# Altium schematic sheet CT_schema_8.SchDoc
size 385 x 278 mm
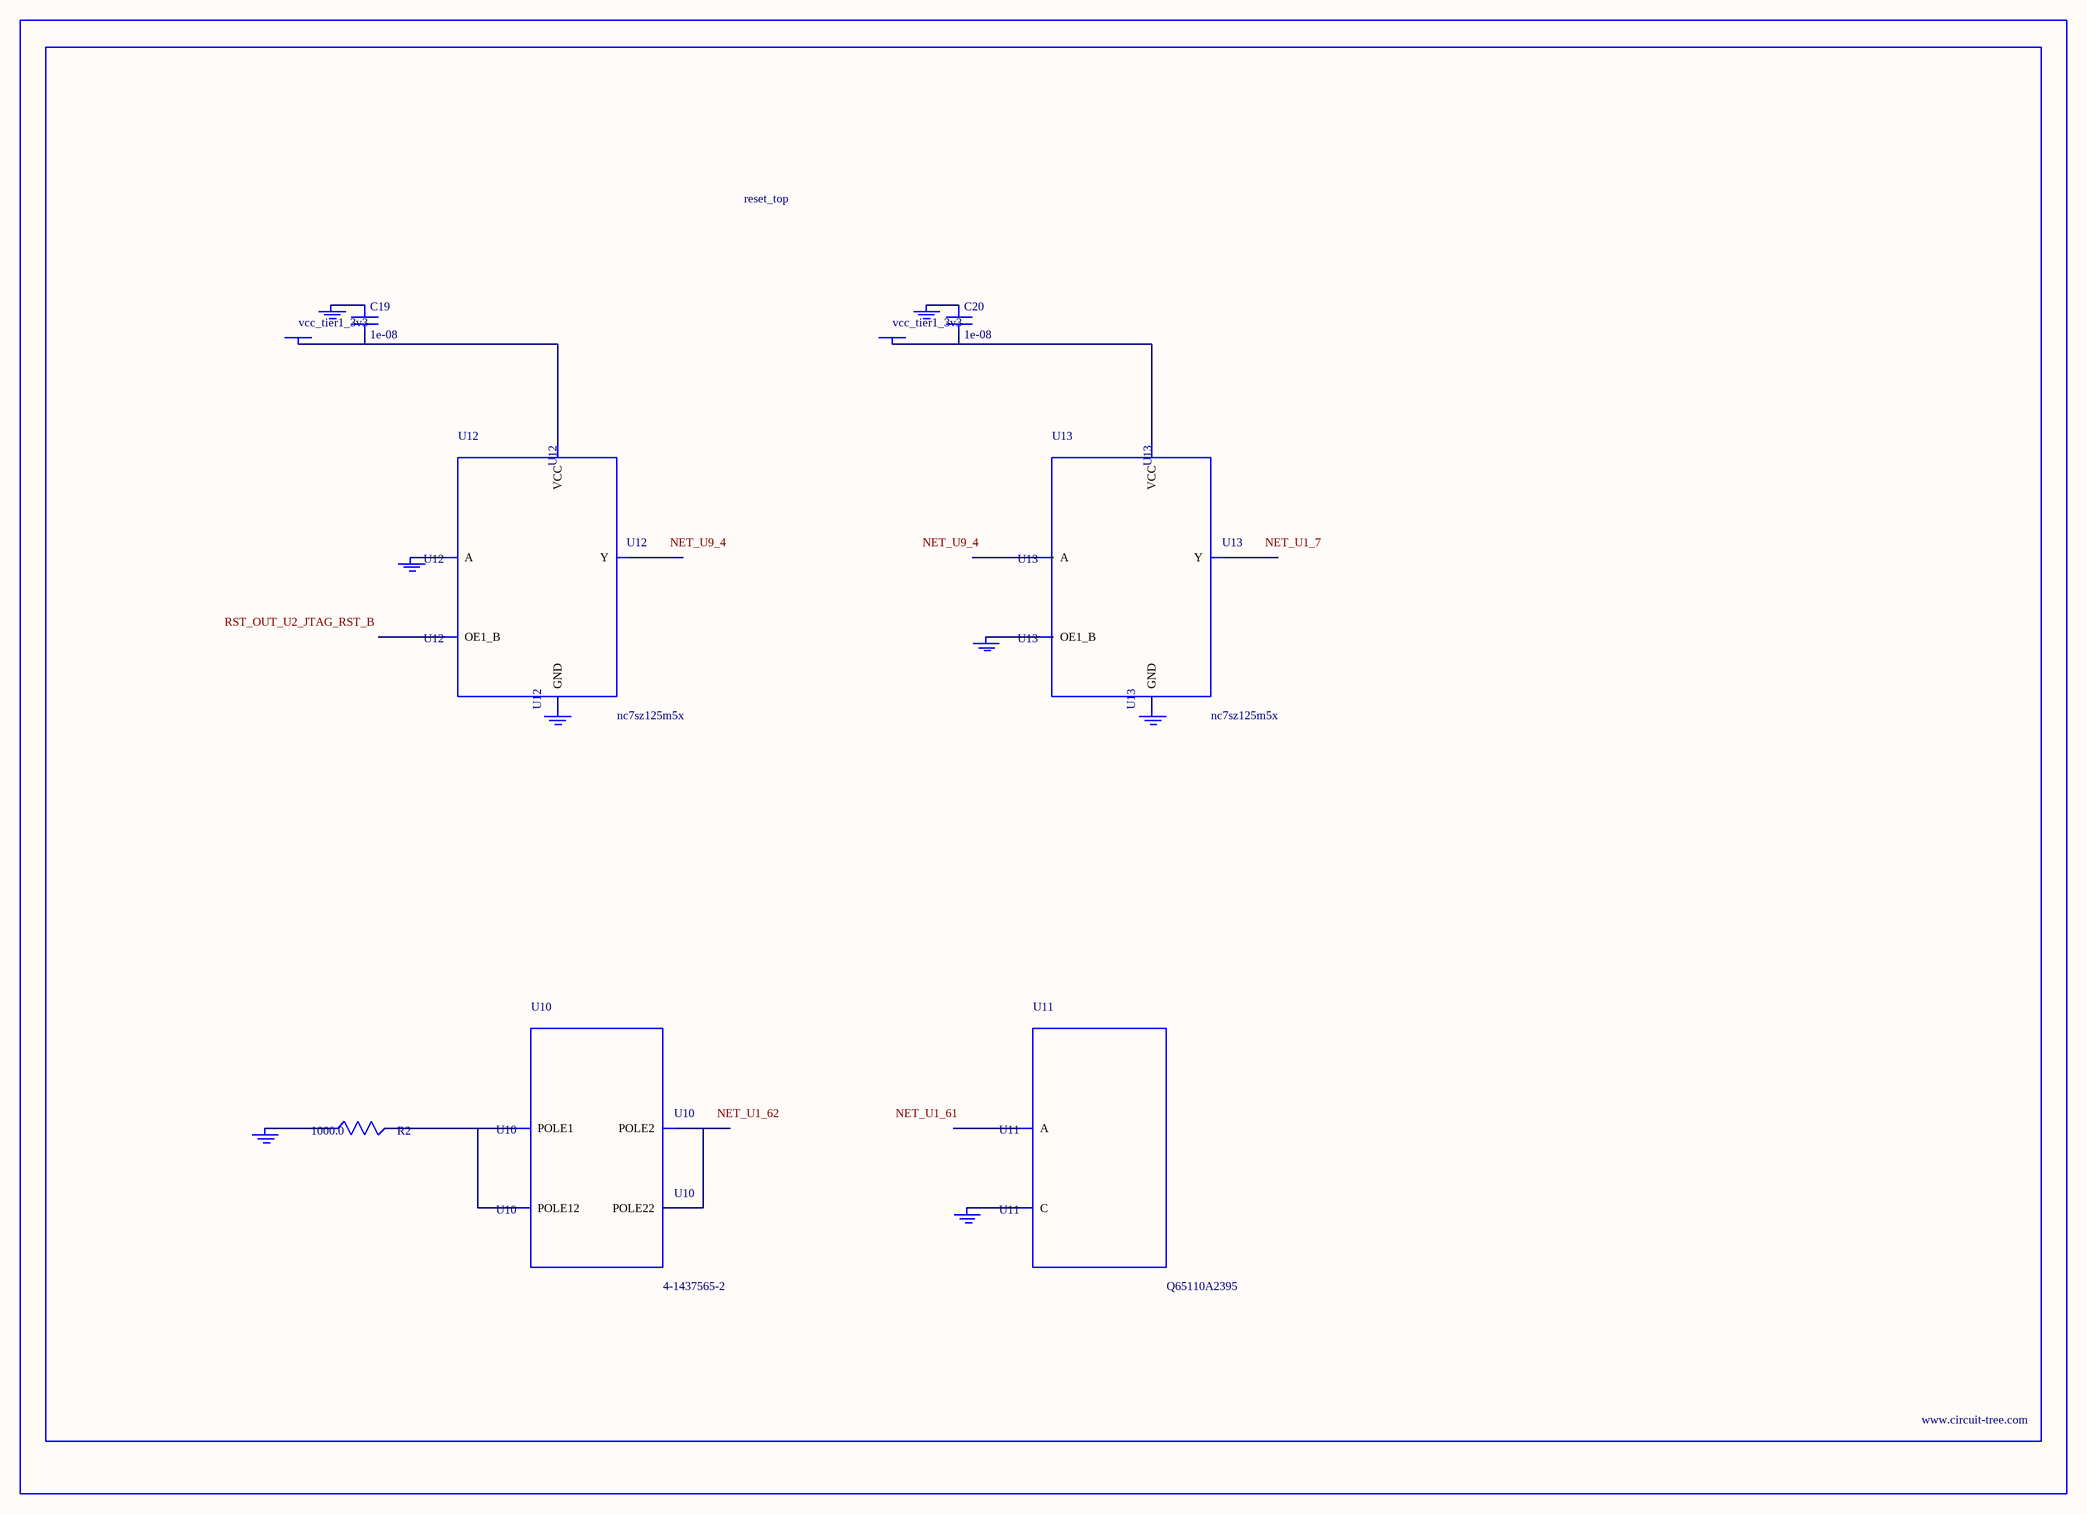
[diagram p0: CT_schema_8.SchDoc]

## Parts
BORDER7  (no value)
C19  1e-08  [C0402]
C20  1e-08  [C0402]
GND_INSTANCE_7_0  (no value)
GND_INSTANCE_7_1  (no value)
GND_INSTANCE_7_2  (no value)
GND_INSTANCE_7_3  (no value)
GND_INSTANCE_7_4  (no value)
GND_INSTANCE_7_5  (no value)
GND_INSTANCE_7_6  (no value)
GND_INSTANCE_7_7  (no value)
POWER_INSTANCE_7_0  vcc_tier1_3v3
POWER_INSTANCE_7_1  vcc_tier1_3v3
R2  1000.0  [R0603]
U10  4-1437565-2  [SW_4-1437565-2]
U11  Q65110A2395  [LGM67K-G1J2-24-Z]
U12  nc7sz125m5x  [NC7SZ125M5X]
U13  nc7sz125m5x  [NC7SZ125M5X]

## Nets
NetC19_1: C19.1 GND_INSTANCE_7_2.0(GND)
NetC19_2: C19.2 POWER_INSTANCE_7_0.0(PWR) U12.5(VCC)
NetC20_1: C20.1 GND_INSTANCE_7_5.0(GND)
NetC20_2: C20.2 POWER_INSTANCE_7_1.0(PWR) U13.5(VCC)
NetGND_INSTANCE_7_0_0: GND_INSTANCE_7_0.0(GND) R2.1
NetGND_INSTANCE_7_1_0: GND_INSTANCE_7_1.0(GND) U11.C
NetGND_INSTANCE_7_3_0: GND_INSTANCE_7_3.0(GND) U12.2(A)
NetGND_INSTANCE_7_4_0: GND_INSTANCE_7_4.0(GND) U12.3(GND)
NetGND_INSTANCE_7_6_0: GND_INSTANCE_7_6.0(GND) U13.1(OE1_B)
NetGND_INSTANCE_7_7_0: GND_INSTANCE_7_7.0(GND) U13.3(GND)
NetR2_2: R2.2 U10.1(POLE1) U10.2(POLE12)
NetU10_3: U10.3(POLE2) U10.4(POLE22)

Not connected (* = marked no-connect by the designer): U11 A; U12 1(OE1_B) 4(Y); U13 2(A) 4(Y)

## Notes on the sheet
- Labels drawn without touching a wire or pin: NET_U1_7, NET_U1_61, NET_U1_62, NET_U9_4, RST_OUT_U2_JTAG_RST_B

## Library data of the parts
BORDER7 = BORDER_PAGE7
C19 C20 = C0402C103K3RAC
GND_INSTANCE_7_0-GND_INSTANCE_7_7 = GND
POWER_INSTANCE_7_0 POWER_INSTANCE_7_1 = PWR
R2 = RC0603JR-071KL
